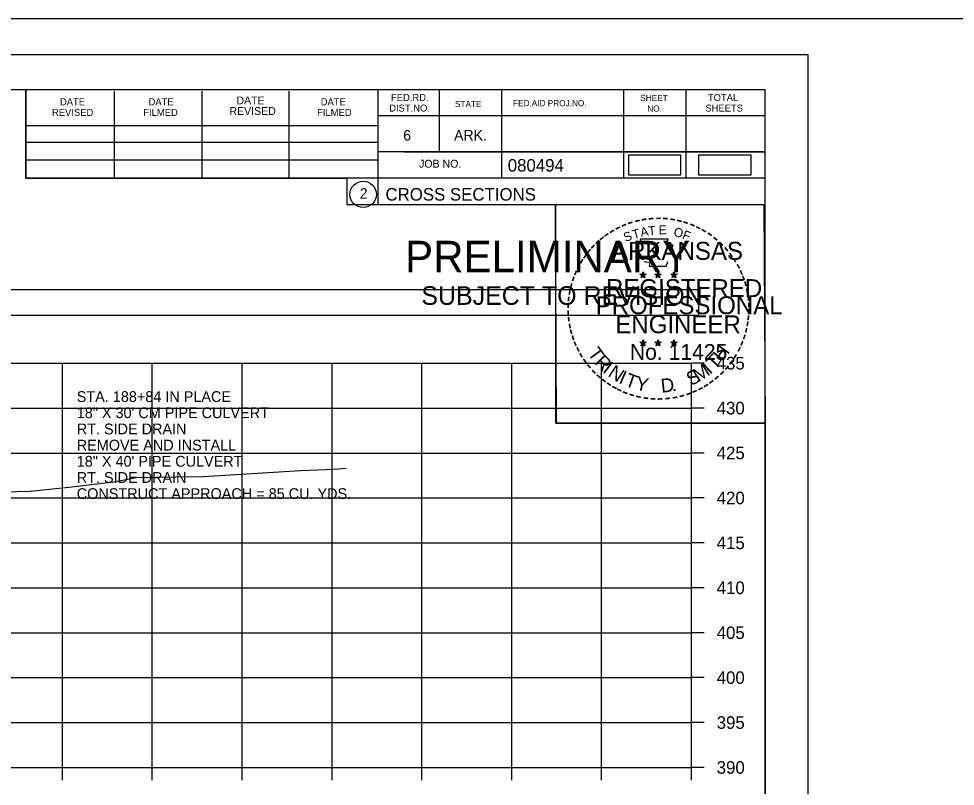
# Model space of a CAD drawing. Extents: x 1376273 to 1384221, y 378927 to 384592.
# Drawn here: x 1379466.3 to 1379570.5, y 380243.7 to 380329.2 of the extents above; entities that cross this region are included whole.
import ezdxf

# ---------------------------------------------------------------- set-up
doc = ezdxf.new("R2010")
doc.units = 0
for name, color, linetype in [('R_Axis', 7, 'Continuous'), ('R_Axis Annot', 7, 'Continuous'), ('R_Border', 7, 'Continuous'), ('R_Border PE', 7, 'Continuous'), ('R_Border Prem', 7, 'Continuous'), ('R_Drive', 7, 'Continuous'), ('R_Exist Surface', 7, 'Continuous'), ('R_Grid', 7, 'Continuous'), ('R_No Plot', 7, 'Continuous'), ('T_Drafting', 7, 'Continuous')]:
    doc.layers.add(name, color=color, linetype=linetype)

msp = doc.modelspace()

# ---------------------------------------------------------------- linework, layer by layer
at = {"layer": 'R_Axis'}
for p, q in [((1379541.15, 380245.82), (1379541.15, 380290.82)), ((1379542.55, 380290.82), (1379541.15, 380290.82)), ((1379542.55, 380285.82), (1379541.15, 380285.82)), ((1379542.55, 380280.82), (1379541.15, 380280.82)), ((1379542.55, 380275.82), (1379541.15, 380275.82)), ((1379542.55, 380270.82), (1379541.15, 380270.82)), ((1379542.55, 380265.82), (1379541.15, 380265.82)), ((1379542.55, 380260.82), (1379541.15, 380260.82)), ((1379542.55, 380255.82), (1379541.15, 380255.82)), ((1379542.55, 380250.82), (1379541.15, 380250.82)), ((1379241.15, 380245.82), (1379541.15, 380245.82)), ((1379471.15, 380244.42), (1379471.15, 380245.82)), ((1379481.15, 380244.42), (1379481.15, 380245.82)), ((1379491.15, 380244.42), (1379491.15, 380245.82)), ((1379501.15, 380244.42), (1379501.15, 380245.82)), ((1379511.15, 380244.42), (1379511.15, 380245.82)), ((1379521.15, 380244.42), (1379521.15, 380245.82)), ((1379531.15, 380244.42), (1379531.15, 380245.82)), ((1379541.15, 380244.42), (1379541.15, 380245.82)), ((1379542.55, 380245.82), (1379541.15, 380245.82))]:
    msp.add_line(p, q, dxfattribs=at)
at = {"layer": 'R_Axis Annot'}
msp.add_lwpolyline([(1379240.17, 380296.18), (1379541.97, 380296.18), (1379541.97, 380298.99), (1379240.17, 380298.99)], close=True, dxfattribs=at)
at = {"layer": 'R_Border'}
for p, q in [((1379233.15, 380321.28), (1379549.33, 380321.28)), ((1379467.07, 380311.4), (1379467.07, 380321.28)), ((1379476.93, 380311.4), (1379476.93, 380321.08)), ((1379486.69, 380311.4), (1379486.69, 380321.08)), ((1379496.37, 380311.4), (1379496.37, 380321.08)), ((1379506.23, 380321.28), (1379506.23, 380308.48)), ((1379513.07, 380321.28), (1379513.07, 380314.34)), ((1379520.01, 380321.28), (1379520.01, 380311.4)), ((1379533.59, 380321.28), (1379533.59, 380311.4)), ((1379540.53, 380321.28), (1379540.53, 380311.4)), ((1379549.33, 380115.82), (1379549.33, 380321.28)), ((1379549.33, 380318.34), (1379506.23, 380318.34)), ((1379549.33, 380318.36), (1379549.33, 380318.36)), ((1379467.07, 380317.26), (1379506.23, 380317.26)), ((1379467.07, 380315.4), (1379506.23, 380315.4)), ((1379549.33, 380314.34), (1379506.23, 380314.34)), ((1379509.19, 380314.34), (1379549.33, 380314.34)), ((1379467.07, 380311.4), (1379467.07, 380313.46)), ((1379467.07, 380313.46), (1379506.23, 380313.46)), ((1379549.33, 380311.4), (1379467.07, 380311.4)), ((1379506.23, 380308.48), (1379549.33, 380308.48))]:
    msp.add_line(p, q, dxfattribs=at)
msp.add_circle((1379504.61, 380309.61), 1.47, dxfattribs=at)
at = {"layer": 'R_Border PE'}
for p, q in [((1379535.41, 380300.73), (1379535.76, 380300.62)), ((1379535.41, 380300.73), (1379535.67, 380300.69)), ((1379535.41, 380300.73), (1379535.65, 380300.61)), ((1379535.76, 380300.99), (1379535.72, 380300.74)), ((1379535.76, 380300.62), (1379535.76, 380300.99)), ((1379535.76, 380300.99), (1379535.81, 380300.74)), ((1379536.11, 380300.73), (1379535.76, 380300.62)), ((1379536.11, 380300.73), (1379535.82, 380300.68)), ((1379536.11, 380300.73), (1379535.9, 380300.63)), ((1379537.08, 380300.73), (1379537.43, 380300.62)), ((1379537.08, 380300.73), (1379537.34, 380300.69)), ((1379537.08, 380300.73), (1379537.32, 380300.61)), ((1379537.43, 380300.99), (1379537.39, 380300.74)), ((1379537.43, 380300.62), (1379537.43, 380300.99)), ((1379537.43, 380300.99), (1379537.48, 380300.74)), ((1379537.78, 380300.73), (1379537.43, 380300.62)), ((1379537.78, 380300.73), (1379537.49, 380300.68)), ((1379537.78, 380300.73), (1379537.57, 380300.63)), ((1379539.2, 380300.98), (1379539.15, 380300.72)), ((1379539.2, 380300.61), (1379539.2, 380300.98)), ((1379539.2, 380300.98), (1379539.24, 380300.73)), ((1379535.55, 380300.33), (1379535.76, 380300.62)), ((1379535.55, 380300.33), (1379535.67, 380300.57)), ((1379535.55, 380300.33), (1379535.76, 380300.54)), ((1379535.97, 380300.33), (1379535.76, 380300.62)), ((1379535.97, 380300.33), (1379535.76, 380300.54)), ((1379535.97, 380300.33), (1379535.84, 380300.62)), ((1379537.22, 380300.33), (1379537.43, 380300.62)), ((1379537.22, 380300.33), (1379537.34, 380300.57)), ((1379537.22, 380300.33), (1379537.43, 380300.54)), ((1379537.64, 380300.33), (1379537.43, 380300.62)), ((1379537.64, 380300.33), (1379537.43, 380300.54)), ((1379537.64, 380300.33), (1379537.51, 380300.62)), ((1379538.85, 380300.72), (1379539.2, 380300.61)), ((1379538.85, 380300.72), (1379539.1, 380300.68)), ((1379538.85, 380300.72), (1379539.08, 380300.6)), ((1379538.98, 380300.31), (1379539.2, 380300.61)), ((1379538.98, 380300.31), (1379539.11, 380300.56)), ((1379538.98, 380300.31), (1379539.19, 380300.53)), ((1379539.41, 380300.31), (1379539.19, 380300.53)), ((1379539.54, 380300.72), (1379539.2, 380300.61)), ((1379539.41, 380300.31), (1379539.2, 380300.61)), ((1379539.54, 380300.72), (1379539.26, 380300.67)), ((1379539.41, 380300.31), (1379539.27, 380300.6)), ((1379539.54, 380300.72), (1379539.34, 380300.62)), ((1379535.41, 380293.16), (1379535.76, 380293.05)), ((1379535.41, 380293.16), (1379535.66, 380293.12)), ((1379535.41, 380293.16), (1379535.65, 380293.04)), ((1379535.54, 380292.75), (1379535.76, 380293.05)), ((1379535.54, 380292.75), (1379535.67, 380293)), ((1379535.54, 380292.75), (1379535.76, 380292.97)), ((1379535.76, 380293.41), (1379535.72, 380293.16)), ((1379535.76, 380293.05), (1379535.76, 380293.41)), ((1379535.76, 380293.41), (1379535.81, 380293.16)), ((1379536.1, 380293.16), (1379535.76, 380293.05)), ((1379535.97, 380292.75), (1379535.76, 380293.05)), ((1379535.97, 380292.75), (1379535.76, 380292.97)), ((1379536.1, 380293.16), (1379535.82, 380293.11)), ((1379535.97, 380292.75), (1379535.83, 380293.04)), ((1379536.1, 380293.16), (1379535.9, 380293.06)), ((1379537.08, 380293.16), (1379537.43, 380293.05)), ((1379537.08, 380293.16), (1379537.33, 380293.12)), ((1379537.08, 380293.16), (1379537.31, 380293.04)), ((1379537.21, 380292.75), (1379537.43, 380293.05)), ((1379537.21, 380292.75), (1379537.34, 380293)), ((1379537.21, 380292.75), (1379537.42, 380292.97)), ((1379537.43, 380293.41), (1379537.39, 380293.16)), ((1379537.64, 380292.75), (1379537.42, 380292.97)), ((1379537.43, 380293.05), (1379537.43, 380293.41)), ((1379537.43, 380293.41), (1379537.48, 380293.16)), ((1379537.77, 380293.16), (1379537.43, 380293.05)), ((1379537.64, 380292.75), (1379537.43, 380293.05)), ((1379537.77, 380293.16), (1379537.49, 380293.11)), ((1379537.64, 380292.75), (1379537.5, 380293.04)), ((1379537.77, 380293.16), (1379537.57, 380293.06)), ((1379538.84, 380293.15), (1379539.19, 380293.04)), ((1379538.84, 380293.15), (1379539.1, 380293.11)), ((1379538.84, 380293.15), (1379539.08, 380293.03)), ((1379538.98, 380292.74), (1379539.19, 380293.04)), ((1379538.98, 380292.74), (1379539.1, 380292.99)), ((1379538.98, 380292.74), (1379539.19, 380292.96)), ((1379539.19, 380293.4), (1379539.15, 380293.15)), ((1379539.19, 380293.04), (1379539.19, 380293.4)), ((1379539.19, 380293.4), (1379539.24, 380293.15)), ((1379539.54, 380293.15), (1379539.19, 380293.04)), ((1379539.41, 380292.74), (1379539.19, 380293.04)), ((1379539.41, 380292.74), (1379539.19, 380292.96)), ((1379539.54, 380293.15), (1379539.25, 380293.1)), ((1379539.41, 380292.74), (1379539.27, 380293.03)), ((1379539.54, 380293.15), (1379539.34, 380293.05))]:
    msp.add_line(p, q, dxfattribs=at)
for points in [[(1379535.45, 380304.61), (1379535.72, 380303.78)], [(1379538.96, 380303.69), (1379539.11, 380303.97), (1379538.42, 380303.95), (1379538.57, 380304.61), (1379535.45, 380304.61)], [(1379535.95, 380302.19), (1379535.95, 380302.1), (1379536.51, 380302.08), (1379536.45, 380301.61), (1379538.32, 380301.61), (1379538.53, 380302.15)], [(1379535.76, 380300.99), (1379535.97, 380300.33), (1379535.41, 380300.73), (1379536.11, 380300.73), (1379535.55, 380300.33), (1379535.76, 380300.99)], [(1379537.43, 380300.99), (1379537.64, 380300.33), (1379537.08, 380300.73), (1379537.78, 380300.73), (1379537.22, 380300.33), (1379537.43, 380300.99)], [(1379539.2, 380300.98), (1379539.41, 380300.31), (1379538.85, 380300.72), (1379539.54, 380300.72), (1379538.98, 380300.31), (1379539.2, 380300.98)], [(1379535.76, 380293.41), (1379535.97, 380292.75), (1379535.41, 380293.16), (1379536.1, 380293.16), (1379535.54, 380292.75), (1379535.76, 380293.41)], [(1379537.43, 380293.41), (1379537.64, 380292.75), (1379537.08, 380293.16), (1379537.77, 380293.16), (1379537.21, 380292.75), (1379537.43, 380293.41)], [(1379539.19, 380293.4), (1379539.41, 380292.74), (1379538.84, 380293.15), (1379539.54, 380293.15), (1379538.98, 380292.74), (1379539.19, 380293.4)]]:
    msp.add_lwpolyline(points, dxfattribs=at)
for centre, radius in [((1379535.76, 380300.62), 0.172), ((1379535.76, 380300.62), 0.145), ((1379535.76, 380300.62), 0.116), ((1379537.43, 380300.62), 0.172), ((1379537.43, 380300.62), 0.145), ((1379537.43, 380300.62), 0.116), ((1379539.19, 380300.61), 0.172), ((1379539.19, 380300.61), 0.145), ((1379535.76, 380300.62), 0.0991), ((1379535.76, 380300.62), 0.0747), ((1379535.76, 380300.62), 0.0495), ((1379535.76, 380300.62), 0.0296), ((1379537.43, 380300.62), 0.0991), ((1379537.43, 380300.62), 0.0747), ((1379537.43, 380300.62), 0.0495), ((1379537.43, 380300.62), 0.0296), ((1379539.19, 380300.61), 0.116), ((1379539.19, 380300.61), 0.0991), ((1379539.19, 380300.61), 0.0747), ((1379539.19, 380300.61), 0.0495), ((1379539.19, 380300.61), 0.0296), ((1379535.76, 380293.05), 0.172), ((1379535.76, 380293.05), 0.145), ((1379535.76, 380293.05), 0.116), ((1379535.76, 380293.05), 0.0991), ((1379535.76, 380293.05), 0.0747), ((1379535.76, 380293.05), 0.0495), ((1379535.76, 380293.05), 0.0296), ((1379537.43, 380293.05), 0.172), ((1379537.43, 380293.05), 0.145), ((1379537.43, 380293.05), 0.116), ((1379537.43, 380293.05), 0.0991), ((1379537.43, 380293.05), 0.0747), ((1379537.43, 380293.05), 0.0495), ((1379537.43, 380293.05), 0.0296), ((1379539.19, 380293.04), 0.172), ((1379539.19, 380293.04), 0.145), ((1379539.19, 380293.04), 0.116), ((1379539.19, 380293.04), 0.0991), ((1379539.19, 380293.04), 0.0747), ((1379539.19, 380293.04), 0.0495), ((1379539.19, 380293.04), 0.0296)]:
    msp.add_circle(centre, radius, dxfattribs=at)
at = {"layer": 'R_Drive'}
for points in [[(1379534.14, 380311.78), (1379539.97, 380311.78), (1379539.97, 380313.97), (1379534.14, 380313.97)], [(1379541.93, 380311.78), (1379547.77, 380311.78), (1379547.77, 380313.96), (1379541.93, 380313.96)]]:
    msp.add_lwpolyline(points, close=True, dxfattribs=at)
at = {"layer": 'R_Exist Surface'}
msp.add_lwpolyline([(1379461.6, 380276.41), (1379467.57, 380276.58), (1379472.18, 380277.05), (1379476.86, 380277.62), (1379479.36, 380278.1), (1379483.76, 380278.16), (1379486.81, 380278.21), (1379497.63, 380278.88), (1379500.5, 380278.99), (1379501.85, 380279.07), (1379502.73, 380279.12)], dxfattribs=at)
at = {"layer": 'R_Grid'}
for p, q in [((1379241.15, 380290.82), (1379541.15, 380290.82)), ((1379471.15, 380245.82), (1379471.15, 380290.82)), ((1379481.15, 380245.82), (1379481.15, 380290.82)), ((1379491.15, 380245.82), (1379491.15, 380290.82)), ((1379501.15, 380245.82), (1379501.15, 380290.82)), ((1379511.15, 380245.82), (1379511.15, 380290.82)), ((1379521.15, 380245.82), (1379521.15, 380290.82)), ((1379531.15, 380245.82), (1379531.15, 380290.82)), ((1379541.15, 380245.82), (1379541.15, 380290.82)), ((1379241.15, 380285.82), (1379541.15, 380285.82)), ((1379241.15, 380280.82), (1379541.15, 380280.82)), ((1379241.15, 380275.82), (1379541.15, 380275.82)), ((1379241.15, 380270.82), (1379541.15, 380270.82)), ((1379241.15, 380265.82), (1379541.15, 380265.82)), ((1379241.15, 380260.82), (1379541.15, 380260.82)), ((1379241.15, 380255.82), (1379541.15, 380255.82)), ((1379241.15, 380250.82), (1379541.15, 380250.82)), ((1379241.15, 380245.82), (1379541.15, 380245.82))]:
    msp.add_line(p, q, dxfattribs=at)
at = {"layer": 'R_No Plot'}
for p, q in [((1379220.75, 380325.17), (1379554.08, 380325.17)), ((1379525.36, 380286.02), (1379525.36, 380286.02))]:
    msp.add_line(p, q, dxfattribs=at)
for points in [[(1379220.74, 380325.17), (1379554.08, 380325.17), (1379554.08, 380111.84), (1379220.74, 380111.84)], [(1379467.07, 380321.28), (1379467.07, 380311.4), (1379502.8, 380311.4), (1379502.8, 380308.48), (1379526, 380308.48), (1379526, 380284.15), (1379549.33, 380284.15), (1379549.33, 380115.82), (1379233.15, 380115.82), (1379233.15, 380321.28)], [(1379526, 380308.48), (1379549.21, 380308.48), (1379549.33, 380284.15), (1379526.12, 380284.15)]]:
    msp.add_lwpolyline(points, close=True, dxfattribs=at)
at = {"layer": 'T_Drafting'}
msp.add_line((1379599.33, 380329.16), (1379233.15, 380329.16), dxfattribs=at)

# ---------------------------------------------------------------- texts
at = {"layer": 'R_Axis Annot'}
for s, height, p in [('435', 1.4, (1379543.95, 380290.12)), ('STA. 188+84 IN PLACE', 1.2, (1379472.74, 380286.5)), ('430', 1.4, (1379543.95, 380285.12)), ('18" X 30\' CM PIPE CULVERT', 1.2, (1379472.74, 380284.7)), ('RT. SIDE DRAIN', 1.2, (1379472.74, 380282.9)), ('REMOVE AND INSTALL', 1.2, (1379472.74, 380281.1)), ('425', 1.4, (1379543.95, 380280.12)), ('18" X 40\' PIPE CULVERT', 1.2, (1379472.74, 380279.3)), ('RT. SIDE DRAIN', 1.2, (1379472.74, 380277.5)), ('CONSTRUCT APPROACH = 85 CU. YDS.', 1.2, (1379472.74, 380275.7)), ('420', 1.4, (1379543.95, 380275.12)), ('415', 1.4, (1379543.95, 380270.12)), ('410', 1.4, (1379543.95, 380265.12)), ('405', 1.4, (1379543.95, 380260.12)), ('400', 1.4, (1379543.95, 380255.12)), ('395', 1.4, (1379543.95, 380250.12)), ('390', 1.4, (1379543.95, 380245.12))]:
    msp.add_text(s, height=height, dxfattribs=at).set_placement(p)
at = {"layer": 'R_Border'}
for s, height, p in [('FED.RD.', 0.782, (1379507.71, 380320)), ('SHEET', 0.684, (1379535.45, 380320)), ('TOTAL', 0.782, (1379542.97, 380320)), ('DATE', 0.782, (1379470.87, 380319.52)), ('DATE', 0.782, (1379480.73, 380319.52)), ('DATE', 0.879, (1379490.51, 380319.62)), ('DATE', 0.782, (1379499.89, 380319.52)), ('DIST.NO.', 0.782, (1379507.51, 380318.82)), ('STATE', 0.684, (1379514.83, 380319.32)), ('FED.AID PROJ.NO.', 0.684, (1379521.29, 380319.42)), ('NO.', 0.684, (1379536.23, 380318.82)), ('SHEETS', 0.782, (1379542.69, 380318.82)), ('REVISED', 0.782, (1379469.99, 380318.34)), ('FILMED', 0.782, (1379480.15, 380318.34)), ('REVISED', 0.879, (1379489.73, 380318.44)), ('FILMED', 0.782, (1379499.49, 380318.34)), ('6', 1.17, (1379509.07, 380315.6)), ('ARK.', 1.172, (1379514.73, 380315.6)), ('JOB NO.', 0.879, (1379510.83, 380312.58)), ('080494', 1.4, (1379520.7, 380312.14)), ('2', 1.17, (1379504.23, 380309.13)), ('CROSS SECTIONS', 1.4, (1379507.09, 380308.91))]:
    msp.add_text(s, height=height, rotation=360, dxfattribs=at).set_placement(p)
at = {"layer": 'R_Border PE'}
for s, height, rotation, p in [('-', 1.6, 5.8968, (1379536.36, 380306.25)), ('-', 1.6, 0.1862, (1379537.13, 380306.32)), ('-', 1.6, 357.743, (1379537.85, 380306.31)), ('-', 1.6, 28.7918, (1379532.93, 380305.15)), ('-', 1.6, 24.3072, (1379533.57, 380305.47)), ('-', 1.6, 19.1761, (1379534.2, 380305.74)), ('-', 1.6, 13.6301, (1379534.95, 380305.98)), ('A', 1, 11.2132, (1379535.55, 380304.87)), ('-', 1.6, 10.2193, (1379535.63, 380306.14)), ('T', 1, 6.0228, (1379536.4, 380305.04)), ('E', 1, 0.8323, (1379537.5, 380305.15)), ('-', 1.6, 352.1617, (1379538.6, 380306.25)), ('-', 1.6, 347.2049, (1379539.32, 380306.14)), ('-', 1.6, 342.3362, (1379539.95, 380305.99)), ('-', 1.6, 337.8551, (1379540.69, 380305.76)), ('-', 1.6, 334.1211, (1379541.32, 380305.49)), ('-', 1.6, 38.9507, (1379531.28, 380304.01)), ('-', 1.6, 36.2317, (1379531.76, 380304.39)), ('-', 1.6, 34.0636, (1379532.34, 380304.78)), ('S', 1, 21.594, (1379533.81, 380304.29)), ('T', 1, 16.4036, (1379534.72, 380304.62)), ('O', 1, 350.4515, (1379539.11, 380304.94)), ('F', 1, 340.0707, (1379540.06, 380304.71)), ('-', 1.6, 329.6409, (1379541.9, 380305.21)), ('-', 1.6, 325.8627, (1379542.54, 380304.85)), ('-', 1.6, 320.5297, (1379543.15, 380304.42)), ('-', 1.6, 48.423, (1379530.4, 380303.11)), ('-', 1.6, 42.9622, (1379530.85, 380303.59)), ('ARKANSAS', 2, 360, (1379532.31, 380302.32)), ('-', 1.6, 315.5786, (1379543.75, 380303.93)), ('-', 1.6, 54.2325, (1379529.59, 380302.06)), ('-', 1.6, 50.6142, (1379530, 380302.63)), ('-', 1.6, 309.8797, (1379544.32, 380303.38)), ('-', 1.6, 306.6522, (1379544.84, 380302.78)), ('-', 1.6, 62.8713, (1379528.95, 380300.92)), ('-', 1.6, 58.0706, (1379529.26, 380301.53)), ('-', 1.4, 303.6753, (1379545.33, 380302.21)), ('-', 1.6, 299.6684, (1379545.65, 380301.61)), ('-', 1.6, 67.7743, (1379528.69, 380300.31)), ('-', 1.6, 294.6628, (1379545.97, 380300.99)), ('-', 1.6, 75.461, (1379528.27, 380298.97)), ('-', 1.6, 72.3945, (1379528.47, 380299.68)), ('REGISTERED', 2, 360, (1379531.63, 380298.17)), ('DWB', 0.01, 360, (1379535.75, 380300.62)), ('DWB', 0.01, 360, (1379537.42, 380300.62)), ('DWB', 0.01, 360, (1379539.18, 380300.61)), ('-', 1.6, 290.5728, (1379546.23, 380300.42)), ('-', 1.6, 285.1233, (1379546.46, 380299.84)), ('-', 1.6, 81.2013, (1379528.14, 380298.25)), ('-', 1.6, 280.5493, (1379546.66, 380299.1)), ('-', 1.6, 85.1863, (1379528.06, 380297.56)), ('PROFESSIONAL', 2, 360, (1379530.48, 380296.27)), ('-', 1.6, 276.5962, (1379546.82, 380298.33)), ('-', 1.6, 94.1959, (1379528.07, 380296.14)), ('-', 1.6, 89.0622, (1379528.04, 380296.86)), ('-', 1.6, 274.3301, (1379546.88, 380297.61)), ('-', 1.6, 269.9407, (1379546.92, 380296.97)), ('-', 1.6, 98.9479, (1379528.15, 380295.47)), ('ENGINEER', 2, 360, (1379532.67, 380294.15)), ('-', 1.6, 263.5172, (1379546.9, 380296.31)), ('-', 1.6, 101.7149, (1379528.28, 380294.74)), ('-', 1.6, 105.4578, (1379528.44, 380294.14)), ('-', 1.6, 255.7626, (1379546.72, 380294.98)), ('-', 1.6, 260.9953, (1379546.83, 380295.65)), ('-', 1.6, 109.0874, (1379528.66, 380293.51)), ('-', 1.6, 252.8681, (1379546.54, 380294.26)), ('-', 1.6, 114.0643, (1379528.91, 380292.91)), ('-', 1.6, 115.7289, (1379529.22, 380292.3)), ('T', 1.54, 306.0406, (1379529.52, 380291.89)), ('No. 11425', 1.757, 360, (1379534.29, 380291.19)), ('DWB', 0.01, 360, (1379535.74, 380293.04)), ('DWB', 0.01, 360, (1379537.41, 380293.04)), ('DWB', 0.01, 360, (1379539.18, 380293.03)), ('H', 1.54, 54.6088, (1379544.64, 380290.92)), ('-', 1.6, 244.6197, (1379546.05, 380292.95)), ('-', 1.6, 247.8887, (1379546.31, 380293.58)), ('-', 1.6, 120.4471, (1379529.57, 380291.71)), ('R', 1.54, 314.005, (1379530.28, 380290.84)), ('T', 1.54, 46.6444, (1379543.75, 380289.98)), ('-', 1.6, 239.0712, (1379545.66, 380292.2)), ('-', 1.6, 125.8934, (1379529.98, 380291.15)), ('-', 1.6, 130.7181, (1379530.44, 380290.6)), ('I', 1.54, 321.9694, (1379531.18, 380289.91)), ('N', 1.54, 326.5002, (1379531.75, 380289.44)), ('M', 1.54, 32.6563, (1379541.9, 380288.66)), ('I', 1.54, 42.1136, (1379543.19, 380289.5)), ('-', 1.6, 231.2538, (1379544.83, 380290.98)), ('-', 1.6, 233.8452, (1379545.26, 380291.55)), ('-', 1.6, 134.2238, (1379530.96, 380290.05)), ('-', 1.6, 138.9338, (1379531.48, 380289.59)), ('I', 1.54, 335.3603, (1379532.95, 380288.65)), ('T', 1.54, 339.8912, (1379533.62, 380288.32)), ('Y', 1.54, 347.8556, (1379534.83, 380287.88)), ('S', 1.54, 26.9312, (1379541.06, 380288.25)), ('-', 1.6, 221.0851, (1379543.82, 380289.91)), ('-', 1.6, 225.7653, (1379544.35, 380290.42)), ('-', 1.6, 144.6463, (1379532.04, 380289.18)), ('-', 1.6, 148.0898, (1379532.6, 380288.81)), ('-', 1.6, 151.5704, (1379533.18, 380288.49)), ('D', 1.54, 6.3969, (1379537.82, 380287.52)), ('-', 1.6, 212.2491, (1379542.74, 380289.05)), ('-', 1.6, 215.7363, (1379543.28, 380289.44)), ('-', 1.6, 154.6002, (1379533.7, 380288.24)), ('-', 1.6, 158.5612, (1379534.32, 380287.98)), ('-', 1.6, 162.7983, (1379535.01, 380287.77)), ('-', 1.6, 167.5555, (1379535.73, 380287.61)), ('.', 1.54, 13.7642, (1379539.01, 380287.65)), ('-', 1.6, 195.4743, (1379540.26, 380287.87)), ('-', 1.6, 200.7184, (1379540.94, 380288.11)), ('-', 1.6, 204.2516, (1379541.56, 380288.39)), ('-', 1.6, 207.3568, (1379542.18, 380288.7)), ('-', 1.6, 173.1155, (1379536.5, 380287.5)), ('-', 1.6, 176.5183, (1379537.25, 380287.44)), ('-', 1.6, 181.5918, (1379537.99, 380287.46)), ('-', 1.6, 185.8167, (1379538.8, 380287.54)), ('-', 1.6, 191.2858, (1379539.53, 380287.67))]:
    msp.add_text(s, height=height, rotation=rotation, dxfattribs=at).set_placement(p)
at = {"layer": 'R_Border Prem'}
for s, height, p in [('PRELIMINARY', 3.5, (1379509.28, 380300.94)), ('DWB', 0.01, (1379510.02, 380302.79)), ('SUBJECT TO REVISION', 2.0751, (1379511.09, 380297.31))]:
    msp.add_text(s, height=height, rotation=360, dxfattribs=at).set_placement(p)

doc.saveas('drawing.dxf')
